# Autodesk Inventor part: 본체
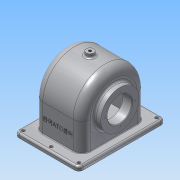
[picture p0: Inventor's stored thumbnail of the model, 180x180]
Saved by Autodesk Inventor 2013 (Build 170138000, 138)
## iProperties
Created: 2015-09
Part Number: 본체
Material: 알루미늄 6061
Document SubType Name: Modeling
Designer: ST3
Density: 2.71 g/cm^3
Mass: 867.365 g
Surface Area: 976.163 cm^2
Volume: 320.061 cm^3
Author: ST3
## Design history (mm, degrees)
sketch "스케치2"
  geometry: L1 (-52, 70)-(52, 70); L2 (52, 70)-(52, -70); L3 (52, -70)-(-52, -70); L4 (-52, -70)-(-52, 70); 1 further point
  constraints: 8 end point, 2 parallel, 1 horizontal, 1 perpendicular
  dimensions: "d0" = 104 distance of L1.start L1.end; "d2" = 140 distance of L1.end L2.end; "d6" = 70 distance from line of point (0, 0) L1; "d7" = 52 distance from line of L4 point (0, 0)
extrude "돌출1" new body sketch "스케치2" distance "d3" = 7; taper "d4" = 0 deg
node "작업 평면2"
sketch "스케치4"
  geometry: L1 (-62.25, 0)-(65.77, 0); L2 (48.5, 20)-(48.5, 31); L3 (48.5, 31)-(38.5, 31); L4 (38.5, 31)-(38.5, 52); L5 (38.5, 52)-(-38.5, 52); L6 (-38.5, 52)-(-38.5, 35.101); L7 (-38.5, 35.101)-(-35.5, 33); L8 (-35.5, 33)-(-35.5, 20); L9 (-35.5, 20)-(-19.5, 20); L10 (-19.5, 20)-(-19.5, 28); L11 (-19.5, 28)-(-33.5, 39.747); L12 (-33.5, 39.747)-(-33.5, 46); L13 (-33.5, 46)-(33.5, 46); L14 (33.5, 46)-(33.5, 20); L15 (33.5, 20)-(48.5, 20); 1 further point
  constraints: 30 end point, 7 parallel, 5 perpendicular, 1 horizontal
  dimensions: "d9" = 0 distance from line of point (0, 0) L1; "d10" = 16 distance between parallel lines of L8 L10; "d12" = 56 diameter of L10.end L1; "d13" = 40 diameter of L15 L1; "d14" = 62 diameter of L3 L1; "d17" = 40 diameter of L9 L1; "d18" = 66 diameter of L7.end L1; "d19" = 50 deg angle of L11 L10; "d21" = 104 diameter of L5 L1; "d25" = 3 distance between parallel lines of L8 L6; "d26" = 5 deg angle of L7 L11; "d27" = 5 distance between parallel lines of L12 L6; "d28" = 67 distance between parallel lines of L12 L14; "d29" = 5 distance between parallel lines of L14 L4; "d30" = 10 distance between parallel lines of L4 L2; "d31" = 38.5 distance from line of point (0, 0) L6; "d34" = 6 distance between parallel lines of L13 L5
revolve "회전1" sketch "스케치4" stored, may be unused: angle "d35" = 90 deg
sketch "스케치7"
  geometry: L1 (45, -70)-(45, 70) reference; L2 (45, -52)-(45, -26.058); L3 (45, 26.058)-(45, 52); L4 (0, -52)-(45, -52); L5 (45, 52)-(0, 52); A1 r 52 centre (0, 0) between (45, 26.058) and (45, -26.058) reference; A2 r 52 centre (0, 0) between (0, -52) and (45, -26.058); A3 r 52 centre (0, 0) between (45, 26.058) and (0, 52); 1 further point
  constraints: 8 end point, 6 point on circle, 3 tangent, 2 centre point, 2 collinear, 2 concentric, 2 point on line, 1 parallel, 1 perpendicular
extrude "돌출3" join sketch "스케치7" stored distance "d38" = 7; taper "d39" = 0 deg
sketch "스케치8"
  geometry: L1 (9.539, 7)-(-9.539, 7) reference; L2 (-52, 7)-(52, 7) reference; L3 (-46, 52)-(-46, 7); L4 (46, 52)-(46, 7); L5 (-46, 7)-(46, 7); A1 r 46 centre (0, 52) between (9.539, 7) and (-9.539, 7) reference; A2 r 46 centre (0, 52) between (-46, 52) and (-9.539, 7); A3 r 46 centre (0, 52) between (9.539, 7) and (46, 52); 1 further point
  constraints: 6 end point, 6 point on circle, 2 centre point, 2 concentric, 2 perpendicular, 2 point on line, 2 tangent, 1 collinear
extrude "돌출4" cut sketch "스케치8" stored distance "d40" = 7; taper "d41" = 0 deg
sketch "스케치9"
  geometry: 1 further point
sketch "스케치10"
  geometry: L1 (-52, 7)-(52, 7) reference; L2 (-46, 52)-(-46, 7); L3 (46, 52)-(46, 7); L4 (-46, 7)-(-9.539, 7); L5 (9.539, 7)-(46, 7); A1 r 46 centre (0, 52) between (9.539, 7) and (-9.539, 7) reference; A2 r 46 centre (0, 52) between (-46, 52) and (-9.539, 7); A3 r 46 centre (0, 52) between (9.539, 7) and (46, 52); 1 further point
  constraints: 8 end point, 6 point on circle, 2 centre point, 2 collinear, 2 concentric, 2 perpendicular, 2 point on line, 2 tangent
extrude "돌출5" cut sketch "스케치10" stored distance "d42" = 7; taper "d43" = 0 deg
node "작업 평면4"
sketch "스케치11"
  geometry: C1 r 6 at (0, 0); 1 further point
  constraints: 1 centre point, 1 coincident
  dimensions: "d45" = 12 diameter of C1
extrude "돌출6" join sketch "스케치11" stored distance "d47" = 7; taper "d48" = 0 deg
sketch "스케치12"
  geometry: 1 further point
sketch "스케치15"
  geometry: C1 r 6 at (0, 0) reference
hole "구멍1" sketch "스케치15" at (0, 0) diameter "d50" = 4.459; stored, may be unused: countersink angle "d54" = 90 deg, drill point angle "d56" = 0 deg; dims "d51" = 20, "d52" = 4, "d53" = 2, "d55" = 8
fillet "모깎기1" dims "d61" = 3
fillet "모깎기3" dims "d63" = 14
fillet "모깎기4" dims "d64" = 9
fillet "모깎기5" dims "d65" = 1
sketch "스케치18"
  geometry: L1 (15.579, -20.03)-(33.421, -20.03); L2 (33.421, -20.03)-(33.421, -23.97); L3 (33.421, -23.97)-(15.579, -23.97); L4 (15.579, -23.97)-(15.579, -20.03); L5 (15.579, -22)-(33.421, -22); L6 (24.5, -23.97)-(24.5, -20.03); L7 (-14, 0)-(-14, -44) reference; L8 (76.5, -52)-(-27.5, -52) reference; 3 further points
  constraints: 4 end point, 4 midpoint, 2 other
  dimensions: "d66" = 38.5 distance between parallel lines of L6 L7; "d67" = 30 distance between parallel lines of L5 L8
extrude "돌출7" join sketch "스케치18" distance "d68" = 0.5; taper "d69" = 0 deg
fillet "모깎기6" dims "d70" = 3
chamfer "모따기1" distance "d71" = 1; stored, may be unused: second distance "d72" = 2, angle "d73" = 45 deg
sketch "스케치19" dims "d74" = 48
  geometry: C1 r 31 at (0, 0) reference; C2 r 21 at (0, 0) reference; 3 further points
  constraints: 1 coincident, 1 horizontal alignment, 2 other
  dimensions: "d76" = 0 vertical distance of point (-24, 0) C1.centre
hole "구멍2" sketch "스케치19" at (-24, 0) diameter "d77" = 2.459; stored, may be unused: countersink angle "d81" = 90 deg, drill point angle "d83" = 118 deg; dims "d78" = 6, "d79" = 4, "d80" = 2, "d82" = 8
sketch "스케치20" dims "d87" = 56
  geometry: C1 r 33 at (0, 0) reference; C2 r 21 at (0, 0) reference; 3 further points
  constraints: 1 coincident, 1 horizontal alignment, 2 other
  dimensions: "d89" = 0 vertical distance of point (28, 0) C1.centre
hole "구멍3" sketch "스케치20" at (28, 0) diameter "d90" = 2.459; stored, may be unused: countersink angle "d94" = 90 deg, drill point angle "d96" = 118 deg; dims "d91" = 7, "d92" = 4, "d93" = 2, "d95" = 9
fillet "모깎기7" dims "d116" = 3
fillet "모깎기8" dims "d117" = 7
fillet "모깎기9" dims "d118" = 7
sketch "스케치24"
  geometry: C1 r 2.5 at (-45, 63); C2 r 2.5 at (45, 63); C3 r 2.5 at (0, 63); C4 r 2.5 at (-45, -63); C5 r 2.5 at (0, -63); C6 r 2.5 at (45, -63); A1 r 4 centre (45, -63) between (45, -67) and (49, -63) reference; A2 r 4 centre (45, 63) between (49, 63) and (45, 67) reference; A3 r 4 centre (-45, 63) between (-45, 67) and (-49, 63) reference; A4 r 4 centre (-45, -63) between (-49, -63) and (-45, -67) reference; 1 further point
  constraints: 6 centre point, 4 coincident
  dimensions: "d119" = 5 diameter of C4; "d121" = 5 diameter of C5; "d122" = 5 diameter of C6; "d123" = 5 diameter of C1; "d124" = 5 diameter of C3; "d125" = 5 diameter of C2; "d127" = 0 vertical distance of C1.centre C3.centre; "d128" = 0 vertical distance of C5.centre A4.centre; "d132" = 0 horizontal distance of point (0, 0) C3.centre; "d133" = 0 horizontal distance of C5.centre point (0, 0)
extrude "돌출10" cut sketch "스케치24" stored distance "d130" = 0.5; taper "d131" = 0 deg
node "솔리드1"
pattern_circular "원형 패턴1" dims angle "d85" = 360 deg
pattern_circular "원형 패턴2" dims angle "d98" = 360 deg
other parameters: "d8" = 52
